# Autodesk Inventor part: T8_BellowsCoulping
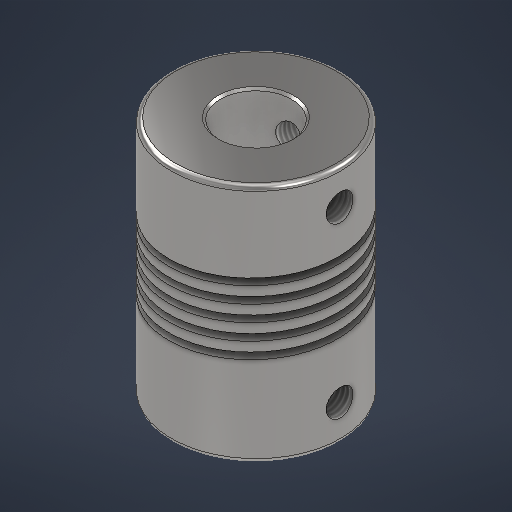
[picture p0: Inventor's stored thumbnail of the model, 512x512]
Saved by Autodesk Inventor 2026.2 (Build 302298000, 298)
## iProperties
Created: 2025-11
Part Number: T8_BellowsCoulping
Material: 스테인리스스틸
Document SubType Name: Modeling
Designer: work
Density: 8 g/cm^3
Appearance: 반연마
Author: work
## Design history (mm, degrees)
sketch "스케치1"
  geometry: C1 r 9.5 at (0, 0); C2 r 4 at (0, 0); 1 further point
  constraints: 2 centre point, 2 coincident
  dimensions: "d0" = 19 diameter of C1; "d1" = 8 diameter of C2
extrude "돌출1" new body sketch "스케치1" distance "d2" = 27; taper "d3" = 0 deg
sketch "스케치2"
  geometry: L1 (27, -4)-(0, -4) reference; L2 (0, -9.5)-(27, -9.5) reference; L3 (9, -4)-(9.75, -4); L4 (9.75, -4)-(9.75, -9.5); L5 (9.75, -9.5)-(9, -9.5); L6 (9, -9.5)-(9, -4); L7 (0, -9.5)-(0, 9.5) reference; L8 (0, 0)-(27, 0); L9 (27, -9.5)-(27, 9.5) reference
  constraints: 10 end point, 2 parallel, 2 point on line, 1 horizontal, 1 midpoint, 1 perpendicular
  dimensions: "d4" = 0.75 distance of L4.end L5.end; "d5" = 9 distance between parallel lines of L7 L6
feature "코일1" sketch "스케치2" pitch "d6" = 1.8; turns "d8" = 5; dims "d7" = 10, "d9" = 0, angle "d10" = 90 deg, angle "d11" = 90 deg, "d12" = 0, "d13" = 0
chamfer "모따기1" distance "d14" = 0.75; stored, may be unused: second distance "d15" = 2, angle "d16" = 80 deg
chamfer "모따기2" distance "d17" = 0.75; stored, may be unused: second distance "d18" = 2, angle "d19" = 80 deg
sketch "스케치3"
  geometry: L1 (0, 0)-(4, 0); C1 r 1.5 at (4, 0)
  constraints: 2 end point, 1 centre point, 1 horizontal
  dimensions: "d20" = 3 diameter of C1; "d21" = 4 distance of L1.start L1.end (computed from d20)
extrude "돌출2" cut sketch "스케치3" extent not by distance; stored distance "d22" = 0; taper "d23" = 0 deg
node "작업 평면1"
feature "스레드1" dims "d27" = 5.792, "d28" = 0
feature "스레드2" dims "d29" = 5.792, "d30" = 0
fillet "모깎기1" dims "d31" = 0.5
chamfer "모따기3" distance "d32" = 0.25; stored, may be unused: second distance "d33" = 2, angle "d34" = 80 deg
node "솔리드1"
pattern_circular "원형 패턴1" dims angle "d25" = 360 deg
mirror "미러1"
node "작업 평면2"
feature "A9D066F2-1C7D-4E18-AEED-F7BC21143FA4" dims "d6" = 1.8, "d7" = 10, "d8" = 50, "d9" = 0, "d10" = 90 deg, "d11" = 90 deg, "d12" = 0, "d13" = 0
